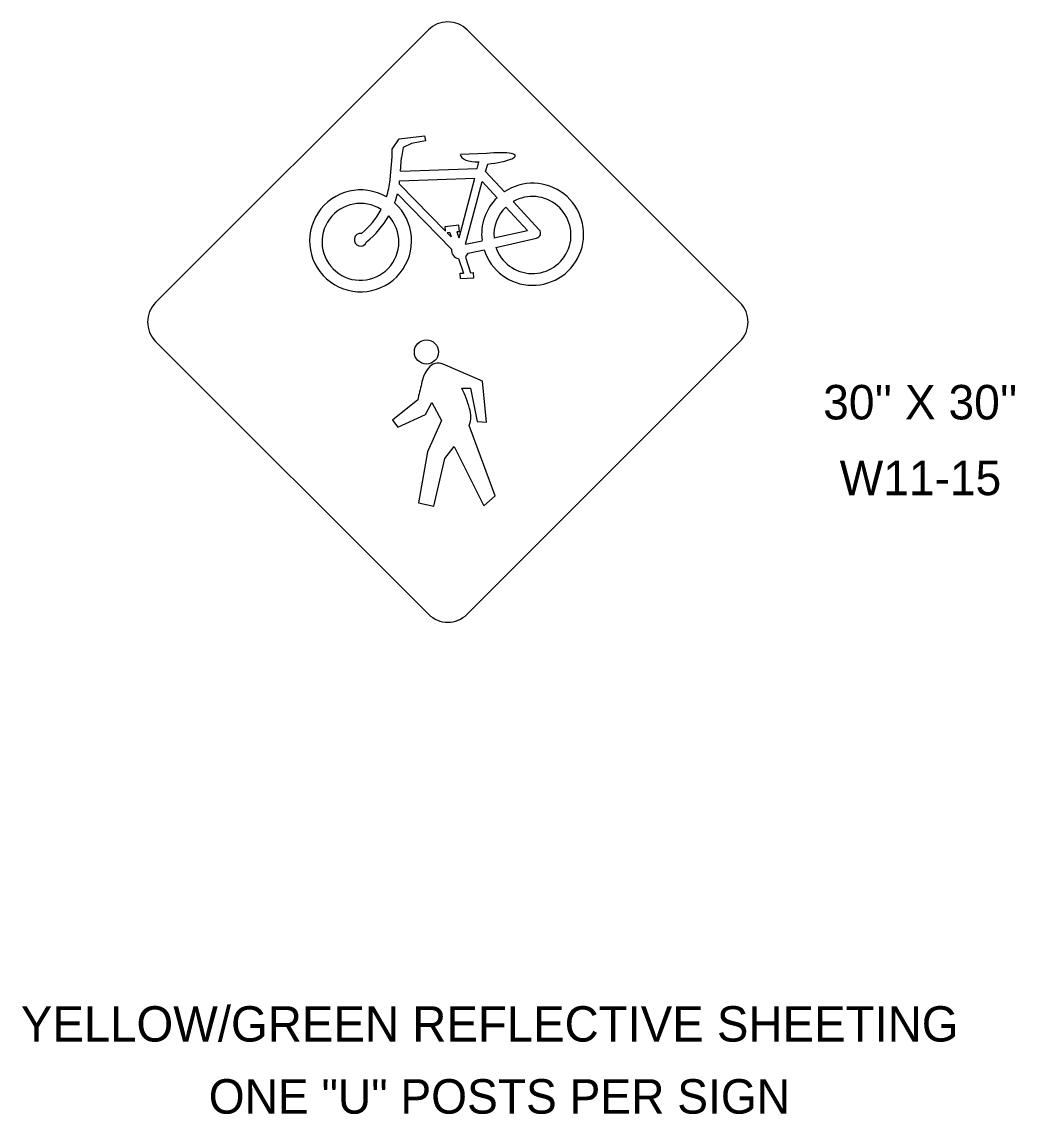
# Model space of a CAD drawing. Extents: x 2088420 to 2091362, y 751309 to 752707.
# Drawn here: x 2089711.7 to 2089859.1, y 752528.7 to 752690.8 of the extents above; entities that cross this region are included whole.
import ezdxf

# ---------------------------------------------------------------- set-up
doc = ezdxf.new("R2010")
doc.units = 0
doc.layers.add('Default', color=7, linetype='Continuous')
doc.layers.add('Prop Sign E', color=7, linetype='Continuous')

msp = doc.modelspace()

# ---------------------------------------------------------------- linework, layer by layer
at = {"layer": 'Prop Sign E'}
for p, q in [((2089772.01, 752689.65), (2089731.54, 752649.18)), ((2089818.24, 752649.18), (2089777.78, 752689.65)), ((2089767.68, 752673.48), (2089771.43, 752673.95)), ((2089771.43, 752673.95), (2089771.59, 752673.18)), ((2089766.62, 752671.94), (2089767.68, 752673.48)), ((2089766.62, 752670.83), (2089766.62, 752671.94)), ((2089768.26, 752672.22), (2089768.04, 752670.69)), ((2089769.48, 752672.79), (2089768.26, 752672.22)), ((2089771.59, 752673.18), (2089769.48, 752672.79)), ((2089766.33, 752667.41), (2089766.62, 752670.83)), ((2089767.87, 752668.7), (2089768.04, 752670.69)), ((2089780.64, 752671.29), (2089776.76, 752671.17)), ((2089767.87, 752668.7), (2089779.27, 752669.09)), ((2089779.27, 752669.09), (2089779.51, 752670.07)), ((2089780.49, 752668.65), (2089780.81, 752669.72)), ((2089767.72, 752666.77), (2089767.74, 752667.27)), ((2089767.74, 752667.27), (2089778.9, 752667.64)), ((2089776.57, 752658.77), (2089778.9, 752667.64)), ((2089777.53, 752657.85), (2089779.99, 752667.16)), ((2089782.21, 752664.74), (2089779.99, 752667.16)), ((2089783.28, 752665.62), (2089780.49, 752668.65)), ((2089774.57, 752659.78), (2089767.71, 752666.78)), ((2089775.44, 752657.12), (2089767.41, 752665.31)), ((2089788.46, 752659.99), (2089784.6, 752664.17)), ((2089786.7, 752659.89), (2089783.5, 752663.35)), ((2089776.53, 752660.66), (2089774.51, 752660.44)), ((2089776.65, 752659.69), (2089776.53, 752660.66)), ((2089774.57, 752659.78), (2089774.51, 752660.48)), ((2089774.56, 752659.93), (2089774.51, 752660.48)), ((2089775.2, 752659.56), (2089774.78, 752659.52)), ((2089775.39, 752658.94), (2089774.78, 752659.52)), ((2089775.18, 752659.57), (2089775.39, 752658.94)), ((2089776.67, 752659.69), (2089776.25, 752659.66)), ((2089776.25, 752659.66), (2089776.55, 752658.79)), ((2089781.74, 752658.79), (2089786.7, 752659.89)), ((2089777.53, 752657.84), (2089779.99, 752658.37)), ((2089782.03, 752657.38), (2089788.07, 752658.75)), ((2089776.49, 752655.7), (2089777.23, 752653.56)), ((2089777.51, 752655.93), (2089778.27, 752653.61)), ((2089777.91, 752656.5), (2089780.27, 752656.99)), ((2089776.73, 752653.53), (2089777.23, 752653.56)), ((2089776.78, 752652.74), (2089776.73, 752653.53)), ((2089776.78, 752652.74), (2089778.75, 752652.87)), ((2089778.27, 752653.61), (2089778.69, 752653.67)), ((2089778.75, 752652.87), (2089778.69, 752653.67)), ((2089731.54, 752643.41), (2089772.01, 752602.95)), ((2089777.78, 752602.95), (2089818.24, 752643.41))]:
    msp.add_line(p, q, dxfattribs=at)
for points in [[(2089776.97, 752636.47), (2089778.27, 752636.47), (2089779.26, 752631.53), (2089780.63, 752631.44), (2089780.04, 752637.54), (2089774.18, 752640.05)], [(2089770.44, 752634.75), (2089766.67, 752631.74), (2089767.46, 752630.69), (2089771.58, 752632.59), (2089772.5, 752634.34), (2089773.95, 752631.68), (2089771.9, 752627.01), (2089770.52, 752619.47), (2089772.83, 752618.99), (2089774.44, 752626.06), (2089775.83, 752627.84), (2089780.25, 752619.02), (2089781.94, 752620.48), (2089778.06, 752630.94)]]:
    msp.add_lwpolyline(points, dxfattribs=at)
for centre, radius, start, end in [((2089774.89, 752686.76), 4.08, 44.9992, 134.9992), ((2089754.68, 752668.49), 11.69, 341.8859, 354.6153), ((2089761.95, 752658.34), 7.56, 59.5246, 48.0822), ((2089787.48, 752659.32), 7.57, 197.722, 123.7298), ((2089761.93, 752658.19), 5.7, 57.416, 42.5809), ((2089754.68, 752668.49), 13.13, 339.845, 345.9917), ((2089787.48, 752659.32), 7.57, 134.2311, 187.1263), ((2089787.45, 752659.21), 5.72, 198.3372, 119.7809), ((2089754.68, 752668.49), 11.69, 309.245, 331.9704), ((2089787.45, 752659.21), 5.72, 133.7203, 184.2487), ((2089754.68, 752668.49), 13.13, 308.4553, 330.6418), ((2089761.95, 752658.5), 0.942, 82.4049, 341.7453), ((2089787.91, 752659.48), 0.75, 282.7291, 42.7112), ((2089776.71, 752656.95), 1.27, 171.8637, 259.7026), ((2089776.71, 752656.95), 1.27, 308.7007, 339.1761), ((2089734.42, 752646.3), 4.08, 134.9992, 224.9992), ((2089815.36, 752646.3), 4.08, 314.9992, 44.9992), ((2089774.89, 752605.83), 4.08, 224.9992, 314.9992)]:
    msp.add_arc(centre, radius, start, end, dxfattribs=at)
for centre, major_axis, ratio, start_param, end_param in [((2089779.49, 752671.25), (2.75, 0.09), 0.433994, 3.141593, 4.712389), ((2089780.7, 752670.51), (4.21, 0.48), 0.185356, 4.712389, 7.853982), ((2089773.46, 752638.45), (0, 1.75), 0.999989, 5.856088, 7.245133), ((2089776.27, 752636.2), (0, 5.36), 0.999989, 0.918357, 1.400152), ((2089812.31, 752626.17), (0, 42.74), 0.999989, 1.312025, 1.368782), ((2089762.81, 752629.39), (0, 15.83), 0.999989, 4.973098, 5.17626), ((2089774.72, 752632.27), (0, -3.59), 0.999989, 1.193544, 1.911048)]:
    msp.add_ellipse(centre, major_axis=major_axis, ratio=ratio, start_param=start_param, end_param=end_param, dxfattribs=at)
msp.add_ellipse((2089771.72, 752641.85), major_axis=(0, -1.79), ratio=0.999989, dxfattribs=at)

# ---------------------------------------------------------------- texts
at = {"layer": 'Default'}
for s, height, p in [("30'' X 30''", 5.1183, (2089830.59, 752631.84)), ('W11-15', 5.118, (2089833.04, 752620.6)), ('YELLOW/GREEN REFLECTIVE SHEETING', 5.2448, (2089711.54, 752539.51)), ('ONE "U" POSTS PER SIGN', 5.1184, (2089739.42, 752528.81))]:
    msp.add_text(s, height=height, dxfattribs=at).set_placement(p)

doc.saveas('drawing.dxf')
